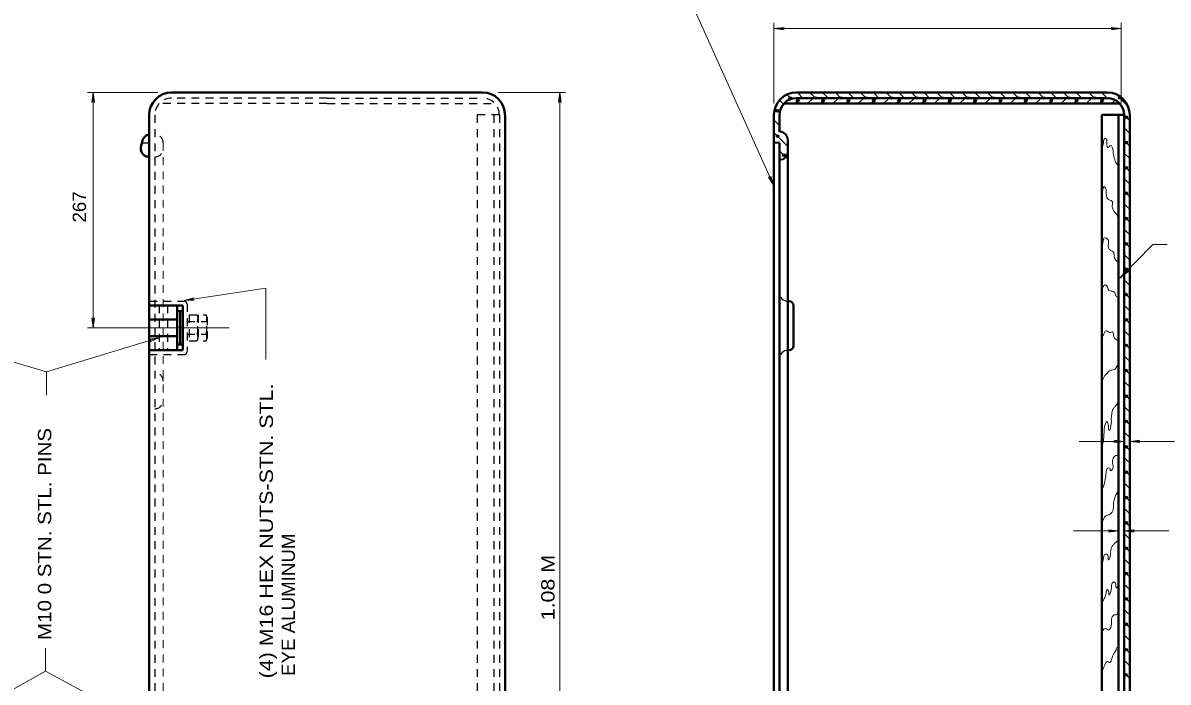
# Model space of a CAD drawing. Extents: x 312583 to 312854, y 144419 to 144597.
# Drawn here: x 312675.3 to 312740.6, y 144485.8 to 144523.4 of the extents above; entities that cross this region are included whole.
import ezdxf
from ezdxf.enums import TextEntityAlignment as Align

# ---------------------------------------------------------------- set-up
doc = ezdxf.new("R2010")
doc.units = 0
doc.header["$LTSCALE"] = 0.3
doc.header["$PDMODE"] = 32
doc.header["$PDSIZE"] = 0.15
doc.linetypes.add('SHORT_DASHED', pattern=[2.7, 1.5, -1.2])
doc.layers.add('1', color=7, linetype='Continuous', lineweight=25)
doc.layers.add('2', color=7, linetype='Continuous', lineweight=13)

msp = doc.modelspace()

# ---------------------------------------------------------------- linework, layer by layer
at = {"layer": '1', "lineweight": 40}
for p, q in [((312692.6448, 144519.4027), (312683.7821, 144519.4027)), ((312692.6448, 144519.4027), (312701.5074, 144519.4027)), ((312728.2641, 144519.4027), (312719.4014, 144519.4027)), ((312728.2641, 144519.0807), (312719.4014, 144519.0807)), ((312728.2641, 144519.4027), (312737.1268, 144519.4027)), ((312728.2641, 144519.0807), (312737.1268, 144519.0807)), ((312728.2641, 144518.7663), (312718.6808, 144518.7663)), ((312728.2641, 144518.7663), (312737.8398, 144518.7663)), ((312682.5018, 144518.1223), (312682.5018, 144466.3723)), ((312702.7878, 144518.1223), (312702.7878, 144466.3723)), ((312718.1211, 144518.1223), (312718.1211, 144466.3723)), ((312718.4431, 144518.1223), (312718.4431, 144517.164)), ((312736.8124, 144518.1223), (312736.8124, 144466.3723)), ((312738.0851, 144518.1223), (312736.8124, 144518.1223)), ((312738.0851, 144518.1223), (312738.0851, 144466.3723)), ((312738.4071, 144518.1223), (312738.4071, 144466.3723)), ((312718.4431, 144516.5277), (312718.4431, 144468.772)), ((312718.9184, 144516.6887), (312718.9184, 144468.611)), ((312682.5018, 144507.2663), (312684.4184, 144507.2663)), ((312684.0964, 144507.2663), (312684.0964, 144504.7057)), ((312684.4184, 144507.2663), (312684.4184, 144504.7057)), ((312718.9184, 144507.504), (312718.9798, 144507.504)), ((312684.0964, 144506.9443), (312684.4184, 144506.9443)), ((312684.2574, 144506.9443), (312684.2574, 144505.0277)), ((312719.2404, 144507.2433), (312719.2404, 144504.9663)), ((312682.5018, 144506.4613), (312684.0964, 144506.4613)), ((312682.5018, 144505.503), (312684.0964, 144505.503)), ((312682.5018, 144504.7057), (312684.4184, 144504.7057)), ((312684.0964, 144505.0277), (312684.4184, 144505.0277)), ((312718.9184, 144504.7057), (312718.9798, 144504.7057))]:
    msp.add_line(p, q, dxfattribs=at)
at = {"layer": '1', "linetype": 'SHORT_DASHED'}
for p, q in [((312692.6448, 144519.0807), (312683.7821, 144519.0807)), ((312692.6448, 144519.0807), (312701.5074, 144519.0807)), ((312692.6448, 144518.7663), (312683.0614, 144518.7663)), ((312692.6448, 144518.7663), (312702.2204, 144518.7663)), ((312682.8238, 144518.1223), (312682.8238, 144466.3723)), ((312701.1931, 144518.1223), (312701.1931, 144466.3723)), ((312702.4658, 144518.1223), (312701.1931, 144518.1223)), ((312702.1514, 144518.1223), (312702.1514, 144466.3723)), ((312702.4658, 144518.1223), (312702.4658, 144466.3723)), ((312682.0801, 144516.5277), (312682.8238, 144516.5277)), ((312682.5018, 144507.504), (312684.4951, 144507.504)), ((312683.0614, 144507.2663), (312683.0614, 144504.7057)), ((312683.5368, 144507.2663), (312683.5368, 144504.7057)), ((312684.6561, 144507.343), (312684.6561, 144504.629)), ((312684.7711, 144506.722), (312685.7448, 144506.722)), ((312684.7711, 144506.722), (312684.7711, 144505.25)), ((312685.2848, 144506.722), (312685.2848, 144505.25)), ((312684.6561, 144506.3387), (312685.7448, 144506.3387)), ((312685.7984, 144506.5917), (312685.7984, 144505.3803)), ((312684.6561, 144505.6333), (312685.7448, 144505.6333)), ((312684.7711, 144505.25), (312685.7448, 144505.25)), ((312682.5018, 144504.468), (312684.4951, 144504.468))]:
    msp.add_line(p, q, dxfattribs=at)
at = {"layer": '1', "lineweight": 13}
for p, q in [((312718.8494, 144519.2877), (312719.1024, 144519.0347)), ((312719.3094, 144518.7663), (312719.6238, 144519.0807)), ((312719.4551, 144519.4027), (312719.7771, 144519.0807)), ((312720.0301, 144518.7663), (312720.3521, 144519.0807)), ((312720.1758, 144519.4027), (312720.4978, 144519.0807)), ((312720.7508, 144518.7663), (312721.0728, 144519.0807)), ((312720.8964, 144519.4027), (312721.2184, 144519.0807)), ((312721.4791, 144518.7663), (312721.7934, 144519.0807)), ((312721.6248, 144519.4027), (312721.9391, 144519.0807)), ((312722.1998, 144518.7663), (312722.5218, 144519.0807)), ((312722.3454, 144519.4027), (312722.6674, 144519.0807)), ((312722.9204, 144518.7663), (312723.2424, 144519.0807)), ((312723.0661, 144519.4027), (312723.3881, 144519.0807)), ((312723.6488, 144518.7663), (312723.9631, 144519.0807)), ((312723.7944, 144519.4027), (312724.1088, 144519.0807)), ((312724.3694, 144518.7663), (312724.6838, 144519.0807)), ((312724.5151, 144519.4027), (312724.8371, 144519.0807)), ((312725.0901, 144518.7663), (312725.4121, 144519.0807)), ((312725.2358, 144519.4027), (312725.5578, 144519.0807)), ((312725.8108, 144518.7663), (312726.1328, 144519.0807)), ((312725.9564, 144519.4027), (312726.2784, 144519.0807)), ((312726.5391, 144518.7663), (312726.8534, 144519.0807)), ((312726.6848, 144519.4027), (312726.9991, 144519.0807)), ((312727.2598, 144518.7663), (312727.5818, 144519.0807)), ((312727.4054, 144519.4027), (312727.7274, 144519.0807)), ((312727.9804, 144518.7663), (312728.3024, 144519.0807)), ((312728.1261, 144519.4027), (312728.4481, 144519.0807)), ((312728.7088, 144518.7663), (312729.0231, 144519.0807)), ((312728.8544, 144519.4027), (312729.1688, 144519.0807)), ((312729.4294, 144518.7663), (312729.7438, 144519.0807)), ((312729.5751, 144519.4027), (312729.8971, 144519.0807)), ((312730.1501, 144518.7663), (312730.4721, 144519.0807)), ((312730.2958, 144519.4027), (312730.6178, 144519.0807)), ((312730.8708, 144518.7587), (312731.1928, 144519.0807)), ((312731.0164, 144519.4027), (312731.3384, 144519.0807)), ((312731.5991, 144518.7663), (312731.9134, 144519.0807)), ((312731.7448, 144519.4027), (312732.0591, 144519.0807)), ((312732.3198, 144518.7663), (312732.6418, 144519.0807)), ((312732.4654, 144519.4027), (312732.7874, 144519.0807)), ((312733.0404, 144518.7663), (312733.3624, 144519.0807)), ((312733.1861, 144519.4027), (312733.5081, 144519.0807)), ((312733.7688, 144518.7663), (312734.0831, 144519.0807)), ((312733.9068, 144519.4027), (312734.2288, 144519.0807)), ((312734.4894, 144518.7663), (312734.8038, 144519.0807)), ((312734.6351, 144519.4027), (312734.9494, 144519.0807)), ((312735.2101, 144518.7663), (312735.5321, 144519.0807)), ((312735.3558, 144519.4027), (312735.6778, 144519.0807)), ((312735.9308, 144518.7663), (312736.2528, 144519.0807)), ((312736.0764, 144519.4027), (312736.3984, 144519.0807)), ((312736.6591, 144518.7663), (312736.9734, 144519.0807)), ((312736.8048, 144519.4027), (312737.1191, 144519.0807)), ((312737.6251, 144519.303), (312738.3534, 144518.5747)), ((312718.1901, 144518.498), (312718.4661, 144518.222)), ((312718.4431, 144518.9657), (312718.6731, 144518.7357)), ((312737.3798, 144518.7663), (312737.5561, 144518.9427)), ((312718.1211, 144517.8463), (312718.4431, 144517.5243)), ((312738.0851, 144518.1147), (312738.4071, 144517.7927)), ((312718.1211, 144517.118), (312718.9184, 144516.3207)), ((312738.0851, 144517.394), (312738.4071, 144517.072)), ((312738.0851, 144516.6733), (312738.4071, 144516.3513)), ((312718.4431, 144516.0753), (312718.7958, 144515.7227)), ((312738.0851, 144515.945), (312738.4071, 144515.6307)), ((312738.0851, 144515.2243), (312738.4071, 144514.9023)), ((312738.0851, 144514.5037), (312738.4071, 144514.1817)), ((312738.0851, 144513.783), (312738.4071, 144513.461)), ((312738.0851, 144513.0547), (312738.4071, 144512.7403)), ((312738.0851, 144512.334), (312738.4071, 144512.012)), ((312738.0851, 144511.6133), (312738.4071, 144511.2913)), ((312738.0851, 144510.8927), (312738.4071, 144510.5707)), ((312738.0851, 144510.1643), (312738.4071, 144509.8423)), ((312738.0851, 144509.4437), (312738.4071, 144509.1217)), ((312738.0851, 144508.723), (312738.4071, 144508.401)), ((312738.0851, 144507.9947), (312738.4071, 144507.6803)), ((312738.0851, 144507.274), (312738.4071, 144506.952)), ((312738.0851, 144506.5533), (312738.4071, 144506.2313)), ((312738.0851, 144505.8327), (312738.4071, 144505.5107)), ((312738.0851, 144505.1043), (312738.4071, 144504.7823)), ((312738.0851, 144504.3837), (312738.4071, 144504.0617)), ((312738.0851, 144503.663), (312738.4071, 144503.341)), ((312738.0851, 144502.9347), (312738.4071, 144502.6203)), ((312738.0851, 144502.214), (312738.4071, 144501.892)), ((312738.0851, 144501.4933), (312738.4071, 144501.1713)), ((312738.0851, 144500.7727), (312738.4071, 144500.4507)), ((312738.0851, 144500.0443), (312738.4071, 144499.73)), ((312738.0851, 144499.3237), (312738.4071, 144499.0017)), ((312738.0851, 144498.603), (312738.4071, 144498.281)), ((312738.0851, 144497.8747), (312738.4071, 144497.5603)), ((312738.0851, 144497.154), (312738.4071, 144496.832)), ((312738.0851, 144496.4333), (312738.4071, 144496.1113)), ((312738.0851, 144495.7127), (312738.4071, 144495.3907)), ((312738.0851, 144494.9843), (312738.4071, 144494.67)), ((312738.0851, 144494.2637), (312738.4071, 144493.9417)), ((312738.0851, 144493.543), (312738.4071, 144493.221)), ((312738.0851, 144492.8223), (312738.4071, 144492.5003)), ((312738.0851, 144492.094), (312738.4071, 144491.772)), ((312738.0851, 144491.3733), (312738.4071, 144491.0513)), ((312738.0851, 144490.6527), (312738.4071, 144490.3307)), ((312738.0851, 144489.9243), (312738.4071, 144489.61)), ((312738.0851, 144489.2037), (312738.4071, 144488.8817)), ((312738.0851, 144488.483), (312738.4071, 144488.161)), ((312738.0851, 144487.7623), (312738.4071, 144487.4403)), ((312738.0851, 144487.034), (312738.4071, 144486.7197)), ((312738.0851, 144486.3133), (312738.4071, 144485.9913))]:
    msp.add_line(p, q, dxfattribs=at)
at = {"layer": '1', "linetype": 'SHORT_DASHED', "lineweight": 13}
msp.add_line((312683.2991, 144516.5277), (312683.2991, 144469.0863), dxfattribs=at)
at = {"layer": '1', "lineweight": 40}
msp.add_lwpolyline([(312737.7708, 144518.1223), (312737.7708, 144466.3723), (312736.8124, 144466.3723)], dxfattribs=at)
for centre, radius, start, end in [((312683.7783, 144518.1249), 1.2778, 90, 180), ((312701.5087, 144518.1249), 1.2778, 0, 90), ((312719.3976, 144518.1249), 1.2778, 90, 180), ((312719.3976, 144518.1249), 0.9583, 90, 180), ((312737.128, 144518.1249), 1.2778, 0, 90), ((312737.128, 144518.1249), 0.9583, 0, 90), ((312718.9823, 144507.2472), 0.2556, 0, 90), ((312718.9823, 144504.9638), 0.2556, 270, 0)]:
    msp.add_arc(centre, radius, start, end, dxfattribs=at)
at = {"layer": '1', "linetype": 'SHORT_DASHED'}
for centre, radius, start, end in [((312683.7783, 144518.1249), 0.9583, 90, 180), ((312701.5087, 144518.1249), 0.9583, 0, 90), ((312682.8199, 144516.5277), 0.4792, 360, 90), ((312682.8199, 144516.2082), 0.4792, 270, 0), ((312684.4977, 144507.343), 0.1597, 0, 90), ((312684.4977, 144504.6277), 0.1597, 270, 0), ((312682.8199, 144502.9513), 0.4792, 360, 90), ((312682.8199, 144501.8549), 0.4792, 270, 0)]:
    msp.add_arc(centre, radius, start, end, dxfattribs=at)
at = {"layer": '1'}
for centre, start, end in [((312718.9184, 144507.9806), 211.97338, 260.00974), ((312718.9184, 144504.2291), 99.15743, 150.42575)]:
    msp.add_arc(centre, 0.4792, start, end, dxfattribs=at)
at = {"layer": '1', "lineweight": 40}
msp.add_spline([(312682.5018, 144515.7303), (312682.2718, 144515.784), (312682.1338, 144515.9067), (312682.0494, 144516.0523), (312682.0724, 144516.497), (312682.2104, 144516.8343), (312682.2871, 144516.911), (312682.5018, 144517.003)], degree=3, dxfattribs=at)
at = {"layer": '1', "lineweight": 13}
for points in [[(312736.8278, 144516.2363), (312736.9121, 144516.5047), (312736.9581, 144516.75), (312737.0424, 144516.7883), (312737.0961, 144516.4817), (312737.1804, 144516.267), (312737.3108, 144516.382), (312737.4104, 144516.2823), (312737.4794, 144515.8453), (312737.5408, 144515.6307), (312737.5944, 144515.4467), (312737.7094, 144515.278), (312737.7478, 144515.1247)], [(312736.8124, 144513.5453), (312736.8584, 144513.783), (312736.9581, 144514.036), (312737.0271, 144513.9517), (312737.0731, 144513.6297), (312737.1421, 144513.3613), (312737.2801, 144513.2617), (312737.3951, 144513.2157), (312737.4104, 144512.9627), (312737.4794, 144512.679), (312737.6098, 144512.5103), (312737.6634, 144512.4413), (312737.7631, 144512.265)], [(312736.8278, 144510.4097), (312736.8431, 144510.6627), (312736.8891, 144510.931), (312736.9428, 144511.0997), (312737.1268, 144511.069), (312737.1958, 144510.8313), (312737.2264, 144510.4787), (312737.3261, 144510.3943), (312737.4641, 144510.3253), (312737.5254, 144510.011), (312737.7478, 144509.7273)], [(312736.8201, 144508.2247), (312736.9121, 144508.355), (312737.0271, 144508.4393), (312737.0961, 144508.3857), (312737.2111, 144508.1403), (312737.4104, 144508.0713), (312737.5561, 144508.0023), (312737.6098, 144507.8183), (312737.7478, 144507.7033)], [(312736.8201, 144505.273), (312736.8201, 144505.388), (312736.9428, 144505.6717), (312737.0424, 144505.8173), (312737.1574, 144505.7867), (312737.2571, 144505.7177), (312737.4411, 144505.756), (312737.4794, 144505.6027), (312737.5408, 144505.4033), (312737.7478, 144505.25)], [(312736.8048, 144502.7123), (312736.8431, 144502.8963), (312736.9428, 144503.1953), (312737.1574, 144503.4483), (312737.3721, 144503.5787), (312737.5254, 144503.6093), (312737.6404, 144503.732), (312737.7478, 144503.9007)], [(312736.8201, 144499.1703), (312736.8891, 144499.4693), (312736.9428, 144500.029), (312737.0041, 144500.4737), (312737.0884, 144500.6423), (312737.1881, 144500.4277), (312737.1881, 144500.2897), (312737.2264, 144500.144), (312737.3568, 144500.5427), (312737.3568, 144500.811), (312737.3951, 144501.1483), (312737.4794, 144501.3937), (312737.5791, 144501.5163), (312737.7478, 144501.7157)], [(312736.8201, 144496.7937), (312736.9044, 144496.947), (312737.0271, 144497.4683), (312737.0578, 144497.729), (312737.1574, 144497.982), (312737.2724, 144497.982), (312737.2954, 144497.8287), (312737.4258, 144497.936), (312737.4258, 144498.2503), (312737.4411, 144498.488), (312737.6098, 144498.7027), (312737.6788, 144498.718), (312737.7478, 144498.7333)], [(312736.8201, 144494.716), (312736.8431, 144494.8463), (312736.9734, 144495.199), (312737.1421, 144495.314), (312737.2264, 144495.3293), (312737.4411, 144495.5517), (312737.4794, 144495.9043), (312737.5408, 144496.257), (312737.6251, 144496.487), (312737.7478, 144496.6557)], [(312736.8048, 144492.4697), (312736.8891, 144492.7457), (312737.0194, 144493.083), (312737.1574, 144493.037), (312737.1881, 144492.7457), (312737.2724, 144492.8837), (312737.3108, 144493.221), (312737.4104, 144493.5353), (312737.5254, 144493.6733), (312737.7401, 144493.8727)], [(312736.8201, 144490.185), (312736.8584, 144490.369), (312736.9581, 144490.5607), (312737.0424, 144490.806), (312737.1421, 144491.0743), (312737.2111, 144490.944), (312737.2264, 144490.76), (312737.3568, 144491.059), (312737.3874, 144491.381), (312737.5101, 144491.5113), (312737.6098, 144491.3273), (312737.6404, 144491.1587), (312737.7554, 144491.2967)], [(312736.7894, 144488.4293), (312736.8431, 144488.6133), (312736.9581, 144488.8357), (312737.0884, 144488.8357), (312737.1881, 144488.7513), (312737.3261, 144488.9123), (312737.3721, 144489.2497), (312737.4104, 144489.518), (312737.5561, 144489.633), (312737.6634, 144489.6407), (312737.7554, 144489.817)], [(312736.8201, 144486.3287), (312736.8584, 144486.482), (312736.9888, 144486.781), (312737.0884, 144486.9497), (312737.1574, 144486.965), (312737.2264, 144486.9037), (312737.3721, 144487.0723), (312737.4948, 144487.4173), (312737.6251, 144487.609), (312737.6711, 144487.7547), (312737.7401, 144487.793)]]:
    msp.add_spline(points, degree=3, dxfattribs=at)
at = {"layer": '1'}
for p in [(312719.0488, 144519.0883), (312719.4781, 144518.935), (312720.4901, 144519.0883), (312720.9271, 144518.935), (312721.9391, 144519.0883), (312722.3684, 144518.935), (312723.3881, 144519.0883), (312723.8174, 144518.935), (312724.8294, 144519.0883), (312725.2588, 144518.935), (312726.2784, 144519.0883), (312726.7078, 144518.935), (312727.7198, 144519.0883), (312728.1491, 144518.935), (312729.1688, 144519.0883), (312729.5981, 144518.935), (312730.6101, 144519.0883), (312731.0471, 144518.935), (312732.0591, 144519.0883), (312732.4884, 144518.935), (312733.5004, 144519.0883), (312733.9374, 144518.935), (312734.9494, 144519.0883), (312735.3788, 144518.935), (312736.3984, 144519.0883), (312736.8278, 144518.935), (312737.8398, 144519.0883), (312718.3281, 144518.36), (312738.2001, 144517.9997), (312718.3281, 144516.9187), (312738.2001, 144516.5583), (312718.6884, 144515.83), (312738.2001, 144515.1093), (312738.2001, 144513.668), (312738.2001, 144512.219), (312738.2001, 144510.77), (312738.2001, 144509.3287), (312738.2001, 144507.8797), (312738.2001, 144506.4383), (312738.2001, 144504.9893), (312738.2001, 144503.548), (312738.2001, 144502.099), (312738.2001, 144500.6577), (312738.2001, 144499.2087), (312738.2001, 144497.7597), (312738.2001, 144496.3183), (312738.2001, 144494.8693), (312738.2001, 144493.428), (312738.2001, 144491.979), (312738.2001, 144490.5377), (312738.2001, 144489.0887), (312738.2001, 144487.6397), (312738.2001, 144486.1983)]:
    msp.add_point(p, dxfattribs=at)
at = {"layer": '2'}
for p, q in [((312718.1211, 144518.7663), (312718.1211, 144523.3663)), ((312718.1211, 144523.0443), (312718.6961, 144523.1133)), ((312718.1211, 144523.0443), (312737.9241, 144523.0443)), ((312718.1211, 144523.0443), (312718.6961, 144522.9753)), ((312718.6961, 144523.1133), (312718.5121, 144523.0443)), ((312718.6961, 144522.9753), (312718.5121, 144523.0443)), ((312737.3491, 144523.1133), (312737.5331, 144523.0443)), ((312737.9241, 144523.0443), (312737.3491, 144523.1133)), ((312737.3491, 144522.9753), (312737.5331, 144523.0443)), ((312737.9241, 144523.0443), (312737.3491, 144522.9753)), ((312737.9241, 144518.7663), (312737.9241, 144523.3663)), ((312683.0001, 144519.4027), (312678.9828, 144519.4027)), ((312679.3048, 144519.4027), (312679.2358, 144518.8277)), ((312679.2358, 144518.8277), (312679.3048, 144519.0117)), ((312679.3048, 144505.986), (312679.3048, 144519.4027)), ((312679.3048, 144519.4027), (312679.3738, 144518.8277)), ((312679.3738, 144518.8277), (312679.3048, 144519.0117)), ((312702.3968, 144519.4027), (312706.2378, 144519.4027)), ((312705.9158, 144519.4027), (312705.8468, 144518.8277)), ((312705.8468, 144518.8277), (312705.9158, 144519.0117)), ((312705.9158, 144465.0997), (312705.9158, 144519.4027)), ((312705.9158, 144519.4027), (312705.9924, 144518.8277)), ((312705.9924, 144518.8277), (312705.9158, 144519.0117)), ((312737.8474, 144508.815), (312738.2001, 144509.275)), ((312738.2001, 144509.275), (312738.1234, 144509.091)), ((312737.8474, 144508.815), (312738.2998, 144509.1753)), ((312738.2998, 144509.1753), (312738.1234, 144509.091)), ((312689.1488, 144508.2553), (312684.4874, 144507.5423)), ((312689.1488, 144508.2553), (312689.1488, 144504.1799)), ((312684.4874, 144507.5423), (312685.0471, 144507.7033)), ((312684.4874, 144507.5423), (312685.0701, 144507.5577)), ((312685.0471, 144507.7033), (312684.8784, 144507.6037)), ((312685.0701, 144507.5577), (312684.8784, 144507.6037)), ((312687.0634, 144505.986), (312678.9828, 144505.986)), ((312679.2358, 144506.561), (312679.3048, 144506.377)), ((312679.3048, 144505.986), (312679.2358, 144506.561)), ((312679.3738, 144506.561), (312679.3048, 144506.377)), ((312679.3048, 144505.986), (312679.3738, 144506.561)), ((312676.6368, 144502.1451), (312676.6368, 144503.4713)), ((312738.0851, 144499.5153), (312735.5321, 144499.5153)), ((312737.5101, 144499.592), (312737.6941, 144499.5153)), ((312738.0851, 144499.5153), (312737.5101, 144499.592)), ((312737.5101, 144499.4463), (312737.6941, 144499.5153)), ((312738.0851, 144499.5153), (312737.5101, 144499.4463)), ((312738.4071, 144499.5153), (312738.9821, 144499.592)), ((312738.4071, 144499.5153), (312740.9601, 144499.5153)), ((312738.4071, 144499.5153), (312738.9821, 144499.4463)), ((312738.9821, 144499.592), (312738.7981, 144499.5153)), ((312738.9821, 144499.4463), (312738.7981, 144499.5153)), ((312737.7708, 144494.4093), (312735.2101, 144494.4093)), ((312737.1881, 144494.4783), (312737.3721, 144494.4093)), ((312737.7708, 144494.4093), (312737.1881, 144494.4783)), ((312737.1881, 144494.3327), (312737.3721, 144494.4093)), ((312737.7708, 144494.4093), (312737.1881, 144494.3327)), ((312738.0851, 144494.4093), (312738.6678, 144494.4783)), ((312738.0851, 144494.4093), (312740.6458, 144494.4093)), ((312738.0851, 144494.4093), (312738.6678, 144494.3327)), ((312738.6678, 144494.4783), (312738.4838, 144494.4093)), ((312738.6678, 144494.3327), (312738.4838, 144494.4093)), ((312676.5908, 144486.413), (312676.5908, 144487.7226))]:
    msp.add_line(p, q, dxfattribs=at)
at = {"layer": '2', "lineweight": 35}
msp.add_line((312718.4431, 144516.5277), (312718.1211, 144516.5277), dxfattribs=at)
at = {"layer": '2'}
for points in [[(312709.3044, 144530.0133), (312710.9528, 144530.0133), (312718.1211, 144514.082)], [(312737.8474, 144508.815), (312739.7319, 144510.7349), (312740.5488, 144510.7349)], [(312670.2044, 144505.3727), (312676.6368, 144503.4713), (312683.0844, 144505.434)], [(312670.2121, 144482.8633), (312676.5908, 144486.413), (312683.0538, 144482.9247)]]:
    msp.add_lwpolyline(points, dxfattribs=at)
for points in [[(312717.9524, 144514.634), (312718.1211, 144514.082), (312717.8144, 144514.5727), (312717.9064, 144514.5497)], [(312682.5094, 144505.3343), (312683.0844, 144505.434), (312682.5554, 144505.1963), (312682.5861, 144505.2883)]]:
    msp.add_lwpolyline(points, close=True, dxfattribs=at)
at = {"layer": '2', "lineweight": 35}
for centre, start, end in [((312718.4393, 144516.6874), 0, 90), ((312718.4405, 144516.0447), 270, 0)]:
    msp.add_arc(centre, 0.4792, start, end, dxfattribs=at)
at = {"layer": '2', "linetype": 'SHORT_DASHED', "lineweight": 25}
for centre, radius, start, end in [((312684.8828, 144506.5291), 0.402, 331.52722, 28.47277), ((312685.3939, 144506.5291), 0.402, 331.52722, 28.47277), ((312683.9171, 144505.986), 1.3651, 345.08374, 14.91626), ((312684.4282, 144505.986), 1.3651, 345.08374, 14.91626), ((312684.8828, 144505.4429), 0.402, 331.52722, 28.47277), ((312685.3939, 144505.4429), 0.402, 331.52722, 28.47277)]:
    msp.add_arc(centre, radius, start, end, dxfattribs=at)

# ---------------------------------------------------------------- texts
at = {"layer": '2'}
for s, width, p in [('267', 1.05, (312678.8977, 144512.8795)), ('(4) M16 HEX NUTS-STN. STL.', 1.2, (312689.5563, 144494.4091)), ('M10 0 STN. STL. PINS', 1.15, (312676.9152, 144494.237)), ('EYE ALUMINUM', 1.05, (312690.8072, 144490.2023)), ('1.08 M', 1.2, (312705.6101, 144491.1778))]:
    msp.add_text(s, height=0.76, rotation=90, dxfattribs=dict(at, width=width)).set_placement(p, align=Align.CENTER)

doc.saveas('drawing.dxf')
